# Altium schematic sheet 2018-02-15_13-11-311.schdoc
size 367 x 190 mm; SheetNumber: 1; SheetTotal: 1
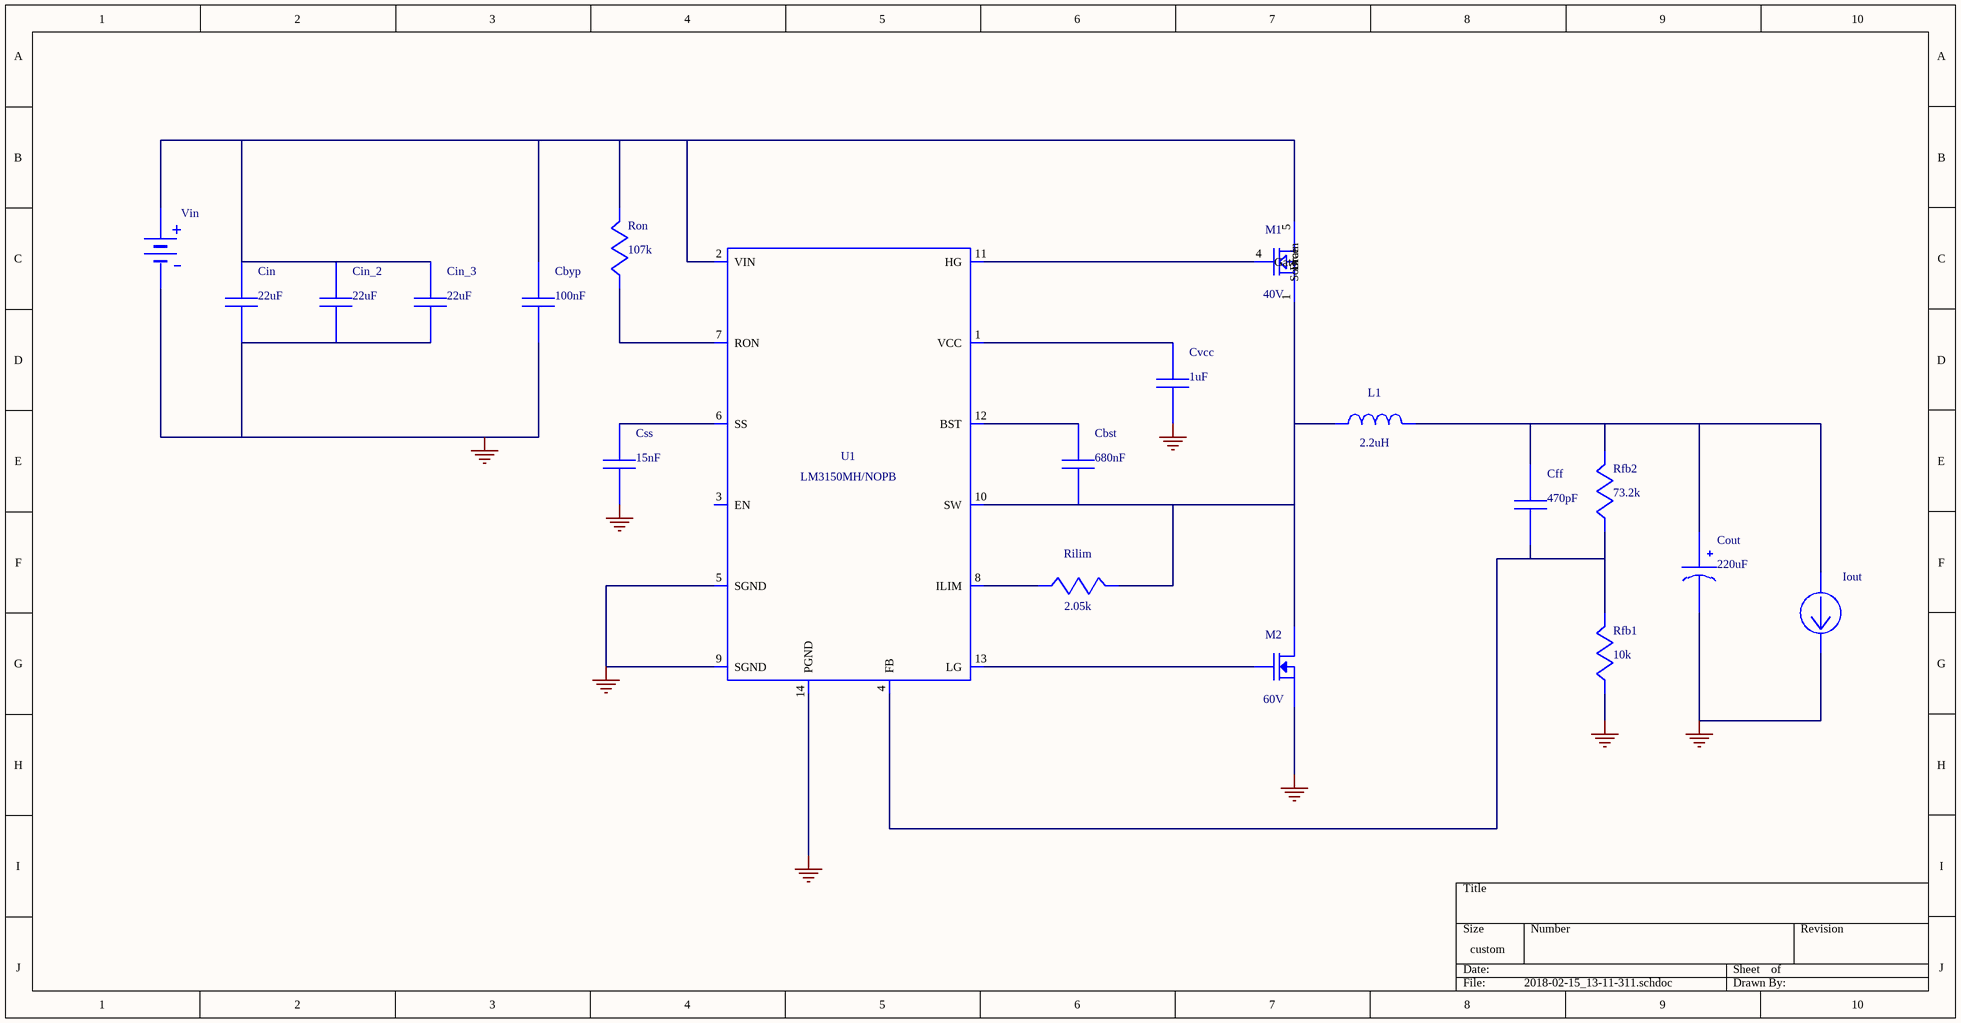
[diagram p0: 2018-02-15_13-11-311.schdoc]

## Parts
Cbst  value 680nF  (hidden comment: ECPU1C684MA5)
Cbyp  value 100nF  (hidden comment: 08055C104MAT2A)
Cff  value 470pF  (hidden comment: C0805C471K5RACTU)
Cin  value 22uF  (hidden comment: C2012X5R1V226M125AC)
Cin_2  value 22uF  (hidden comment: C2012X5R1V226M125AC)
Cin_3  value 22uF  (hidden comment: C2012X5R1V226M125AC)
Cout  value 220uF  (hidden comment: 6SVPE220MW)
Css  value 15nF  (hidden comment: C2012C0G1H153J085AA)
Cvcc  value 1uF  (hidden comment: ECPU1C105MA5)
Iout  WB_CURRENT_LOAD  (value not drawn)
L1  value 2.2uH  (hidden comment: XAL1010-222MEB)
M1  value 40V  (hidden comment: CSD18504Q5A)
M2  value 60V  (hidden comment: CSD18531Q5A)
Rfb1  value 10k  (hidden comment: RR1220P-103-D)
Rfb2  value 73.2k  (hidden comment: ERJ-6ENF7322V)
Rilim  value 2.05k  (hidden comment: ERJ-6ENF2051V)
Ron  value 107k  (hidden comment: ERJ-6ENF1073V)
U1  LM3150MH/NOPB
Vin  WB_BATTERY  (value not drawn)

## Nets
0: Cbyp.2 Cin.2 Cin_2.2 Cin_3.2 Cout.2(-) Css.2 Cvcc.2 Iout.2(-) M2.1(Source) M2.2(Source) M2.3(Source) Rfb1.2 U1.5(SGND) U1.9(SGND) U1.14(PGND) U1.15(DAP) Vin.2(-)
NetCbst_1: Cbst.1 U1.12(BST)
NetCbst_2: Cbst.2 L1.1 M1.1(Source) M1.2(Source) M1.3(Source) M2.5(Drain) M2.6(Drain) M2.7(Drain) M2.8(Drain) M2.9(Drain) Rilim.1 U1.10(SW)
NetCbyp_1: Cbyp.1 Cin.1 Cin_2.1 Cin_3.1 M1.5(Drain) M1.6(Drain) M1.7(Drain) M1.8(Drain) M1.9(Drain) Ron.1 U1.2(VIN) Vin.1(+)
NetCff_1: Cff.1 Cout.1(+) Iout.1(+) L1.2 Rfb2.1
NetCff_2: Cff.2 Rfb1.1 Rfb2.2 U1.4(FB)
NetCss_1: Css.1 U1.6(SS)
NetCvcc_1: Cvcc.1 U1.1(VCC)
NetM1_4: M1.4(Gate) U1.11(HG)
NetM2_4: M2.4(Gate) U1.13(LG)
NetRilim_2: Rilim.2 U1.8(ILIM)
NetRon_2: Ron.2 U1.7(RON)

Not connected (* = marked no-connect by the designer): U1 3(EN)

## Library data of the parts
Cbst = ECPU1C684MA5: Manufacturer Name: Panasonic
Cbyp = 08055C104MAT2A: Manufacturer Name: AVX
Cff = C0805C471K5RACTU: Manufacturer Name: Kemet
Cin Cin_2 Cin_3 = C2012X5R1V226M125AC: C2012X5R1V226M12; Manufacturer Name: TDK
Cout = 6SVPE220MW: Manufacturer Name: Panasonic
Css = C2012C0G1H153J085AA: C2012C0G1H153J08; Manufacturer Name: TDK
Cvcc = ECPU1C105MA5: Manufacturer Name: Panasonic
L1 = XAL1010-222MEB: Manufacturer Name: Coilcraft
M1 = CSD18504Q5A: Manufacturer Name: Texas Instruments
M2 = CSD18531Q5A: Manufacturer Name: Texas Instruments
Rfb1 = RR1220P-103-D: Manufacturer Name: Susumu Co Ltd
Rfb2 = ERJ-6ENF7322V: Manufacturer Name: Panasonic
Rilim = ERJ-6ENF2051V: Manufacturer Name: Panasonic
Ron = ERJ-6ENF1073V: Manufacturer Name: Panasonic
U1 = LM3150MH/NOPB: Manufacturer Name: Texas Instruments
